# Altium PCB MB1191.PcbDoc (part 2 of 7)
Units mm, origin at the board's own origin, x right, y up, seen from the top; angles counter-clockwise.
Board outline 130 x 80 mm, 8 copper layers (Top, F2, F3, F4, F5, F6, F7, Bottom), stack 1.115 mm thick; 358 components, 347 nets, 1452 pads, 1074 vias.
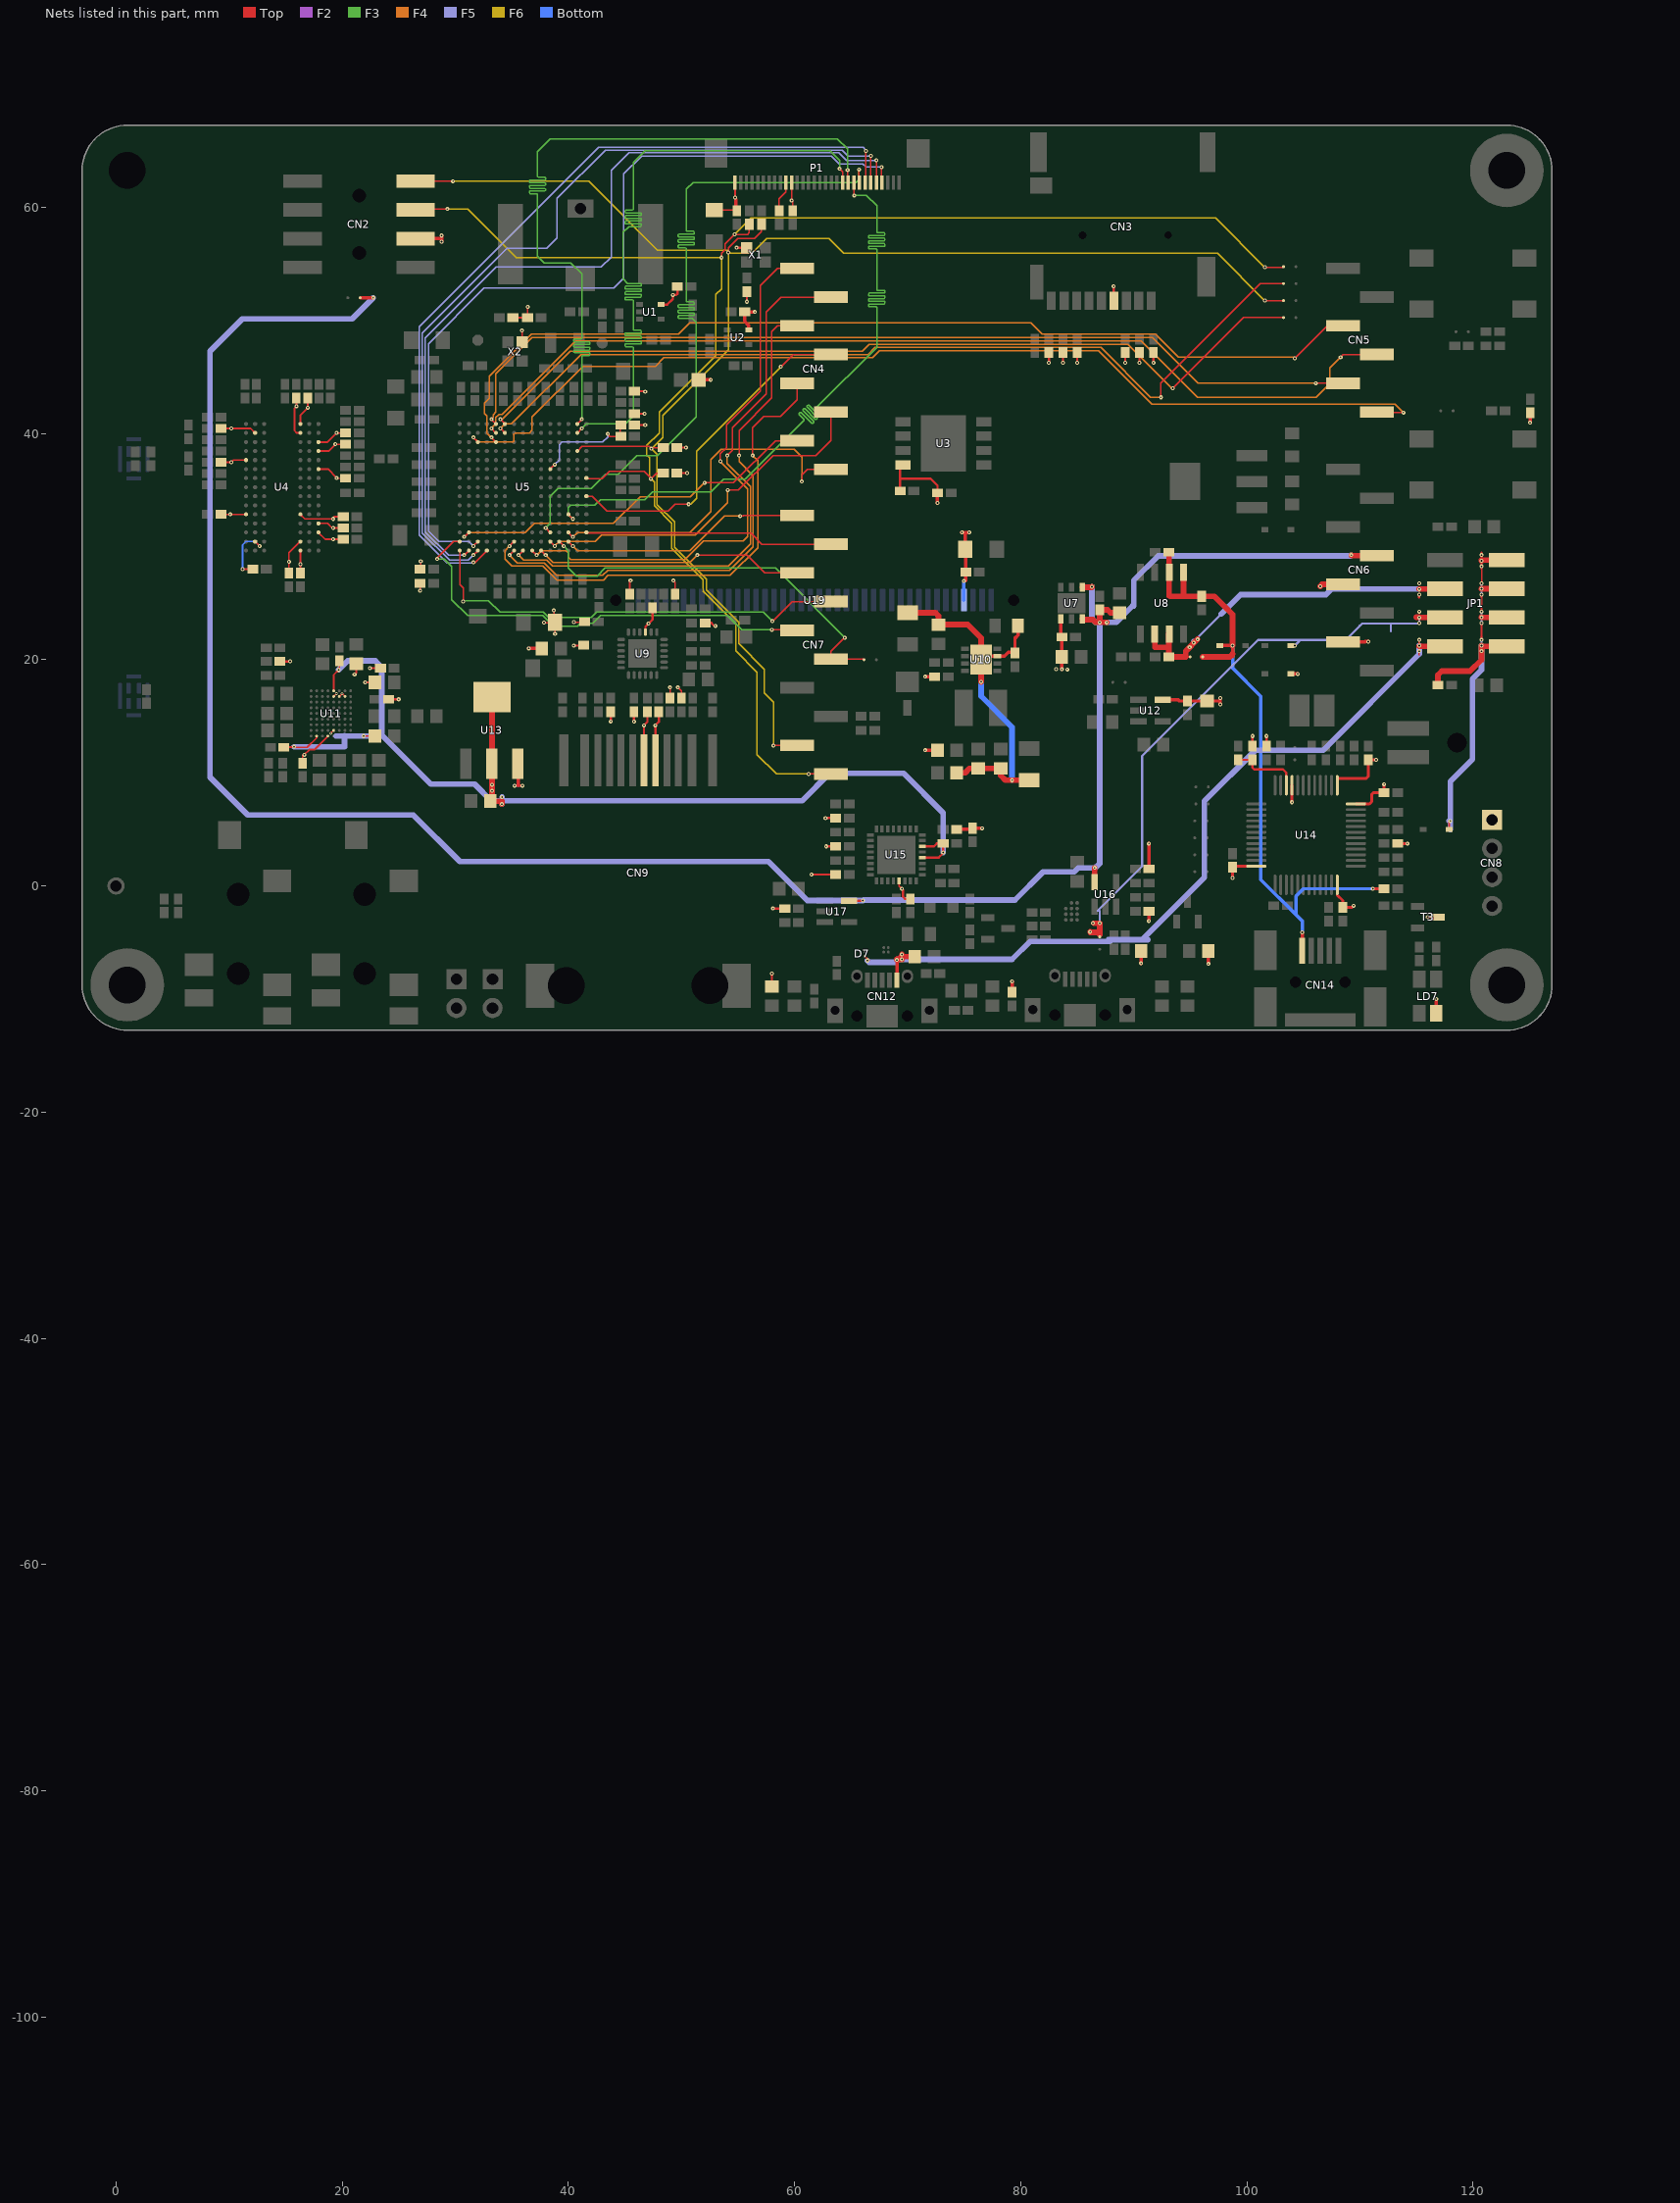
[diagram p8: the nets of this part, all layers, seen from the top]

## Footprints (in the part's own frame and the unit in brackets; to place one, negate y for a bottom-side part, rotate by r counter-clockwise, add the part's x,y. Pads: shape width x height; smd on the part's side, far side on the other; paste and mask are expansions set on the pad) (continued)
QFN24_0R5_4X4 [mm]
  oval 0.69x0.28 smd: 1(-1.9,1.25) 2(-1.9,0.75) 3(-1.9,0.25) 4(-1.9,-0.25) 5(-1.9,-0.75) 6(-1.9,-1.25) 13(1.9,-1.25) 14(1.9,-0.75) 15(1.9,-0.25) 16(1.9,0.25) 17(1.9,0.75) 18(1.9,1.25)
  oval 0.28x0.69 smd: 7(-1.25,-1.9) 8(-0.75,-1.9) 9(-0.25,-1.9) 10(0.25,-1.9) 11(0.75,-1.9) 12(1.25,-1.9) 19(1.25,1.9) 20(0.75,1.9) 21(0.25,1.9) 22(-0.25,1.9) 23(-0.75,1.9) 24(-1.25,1.9)
  rect 2.5x2.5 smd: 25(0,0)
  silkscreen extent -2.82,-2.5 2.5,2.5
QFN32_0R5_5X5 [mm]
  rect 0.6x0.3 smd: 1(-2.3,1.75) 2(-2.3,1.25) 3(-2.3,0.75) 4(-2.3,0.25) 5(-2.3,-0.25) 6(-2.3,-0.75) 7(-2.3,-1.25) 8(-2.3,-1.75) 17(2.3,-1.75) 18(2.3,-1.25) 19(2.3,-0.75) 20(2.3,-0.25) 21(2.3,0.25) 22(2.3,0.75) 23(2.3,1.25) 24(2.3,1.75)
  rect 0.3x0.6 smd: 9(-1.75,-2.3) 10(-1.25,-2.3) 11(-0.75,-2.3) 12(-0.25,-2.3) 13(0.25,-2.3) 14(0.75,-2.3) 15(1.25,-2.3) 16(1.75,-2.3) 25(1.75,2.3) 26(1.25,2.3) 27(0.75,2.3) 28(0.25,2.3) 29(-0.25,2.3) 30(-0.75,2.3) 31(-1.25,2.3) 32(-1.75,2.3)
  rect 3.4x3.4 smd: 33(0,0)
  silkscreen extent -3.05,-3.05 3.05,3.05
"QFP48 7X7" [mm]
  oval 1.803x0.257 smd: 1(-4.4,2.75) 12(-4.4,-2.75) 25(4.4,-2.75) 36(4.4,2.75)
  oval 1.803x0.254 smd: 2(-4.4,2.25) 3(-4.4,1.75) 4(-4.4,1.25) 5(-4.4,0.75) 6(-4.4,0.25) 7(-4.4,-0.25) 8(-4.4,-0.75) 9(-4.4,-1.25) 10(-4.4,-1.75) 11(-4.4,-2.25) 26(4.4,-2.25) 27(4.4,-1.75) 28(4.4,-1.25) 29(4.4,-0.75) 30(4.4,-0.25) 31(4.4,0.25) 32(4.4,0.75) 33(4.4,1.25) 34(4.4,1.75) 35(4.4,2.25)
  oval 0.257x1.803 smd: 13(-2.75,-4.4) 24(2.75,-4.4) 37(2.75,4.4) 48(-2.75,4.4)
  oval 0.254x1.803 smd: 14(-2.25,-4.4) 15(-1.75,-4.4) 16(-1.25,-4.4) 17(-0.75,-4.4) 18(-0.25,-4.4) 19(0.25,-4.4) 20(0.75,-4.4) 21(1.25,-4.4) 22(1.75,-4.4) 23(2.25,-4.4) 38(2.25,4.4) 39(1.75,4.4) 40(1.25,4.4) 41(0.75,4.4) 42(0.25,4.4) 43(-0.25,4.4) 44(-0.75,4.4) 45(-1.25,4.4) 46(-1.75,4.4) 47(-2.25,4.4)
  silkscreen extent -3.96,-2.98 2.97,3.96
RCA_SMD [mm]
  rect 1.6x2.3 hole 1 square mask+0.05: 1(0,0)
  rect 7.1x2.2 smd mask+0.05: 1(3.15,6.2) 1(3.15,-6.2)
  rect 2.2x2.6 smd mask+0.05: 2(6.2,0)
  silkscreen extent -8.5,-5 4.98,5, body extent -8.52,-7 6.5,7, height 12.1
RJ45_HR961160C [mm]
  rect 0.8x4.6 smd: 1(6.579,19.914) 2(4.75,19.914) 11(-4.75,19.914) 12(-6.579,19.914)
  rect 0.6x4.6 smd: 3(3.556,19.914) 4(2.54,19.914) 5(1.524,19.914) 6(0.508,19.914) 7(-0.508,19.914) 8(-1.524,19.914) 9(-2.54,19.914) 10(-3.556,19.914)
  rect 2.5x3.9 smd: 13(8.687,0) 14(-8.687,0)
  round 2.5 hole 3.25 unplated: 15(-6.35,0) 16(6.35,0)
  silkscreen extent -10.67,-5.28 10.67,20.12
SIP1/2.54 [mil]
  round 60 hole 39.37: 1(0,0)
  silkscreen extent -45,-45 45,45
SIP2/2.54 [mil]
  rect 70x70 hole 39.37: 1(0,0)
  round 70 hole 39.37: 2(100,0)
  silkscreen extent -50,-50 150,50
SMDTEST-1MM [mil]
  round 39 smd: 1(0,0)
SO-8 [mil]
  rect 24x60 smd: 1(-75,-107.5) 2(-25,-107.5) 3(25,-107.5) 4(75,-107.5) 5(75,107.5) 6(25,107.5) 7(-25,107.5) 8(-75,107.5)
  silkscreen extent -118,-102 100,68
SOD323/A [mm]
  rect 0.6x0.45 smd: 1(1.143,0) 2(-1.143,0)
  silkscreen extent -0.46,-0.57 0.56,0.57
SOT23 [mm]
  rect 1.2x0.6 smd: 1(-0.9,0.95) 2(-0.9,-0.95) 3(0.9,0)
  silkscreen extent 0.1,-1.5 0.7,1.5
SOT23-5L [mm]
  rect 0.55x1.45 smd: 1(-0.95,-1.075) 2(0,-1.075) 3(0.95,-1.075) 4(0.95,1.075) 5(-0.95,1.075)
  silkscreen extent -1.5,-2.1 1.5,2
SOT353 [mm]
  rect 0.42x0.6 smd: 1(-0.65,-0.95) 2(0,-0.95) 3(0.65,-0.95) 4(0.65,0.95) 5(-0.65,0.95)
  silkscreen extent -1.4,-1.8 1.5,1.8
SOT-223 [mm]
  rect 2.7x1 smd: 1(-2.95,2.3) 2(-2.95,0) 3(-2.95,-2.3)
  rect 2.7x3.3 smd: 4(2.95,0)
  silkscreen extent -3.08,-3.35 1.3,3.47
SSM-104-L-DH [mm]
  rect 1.2x3.4 smd: 1(3.81,-5) 2(3.81,5) 3(1.27,-5) 4(1.27,5) 5(-1.27,-5) 6(-1.27,5) 7(-3.81,-5) 8(-3.81,5)
  round 0.8 hole 1.2 unplated: 9(2.54,0) 10(-2.54,0)
  silkscreen extent -5.08,-3.18 5.08,3.18
TAN-A [mil]
  rect 50x60 smd: 1(55,0) 2(-55,0)
  silkscreen extent -94,-43 102,43
TSM-102-01-F-SH-A [mm]
  round 0 hole 1.73 unplated mask+0.05: 0(0,0)
  rect 3.68x1.27 smd paste+0 mask+0.05: 1(-4.3,1.27) 2(-4.3,-1.27)
  silkscreen extent -2.3,-2.54 7.11,2.54, body extent -5.84,-2.54 7.11,2.54, height 3.05
TSM-104-01-X-DV [mil]
  rect 50x124 smd: 1(-150,-107.5) 2(-150,107.5) 3(-50,-107.5) 4(-50,107.5) 5(50,-107.5) 6(50,107.5) 7(150,-107.52) 8(150,107.52)
  silkscreen extent -200,-100 200,100
USB-MICRO-AB [mm]
  rect 1.35x0.4 smd: 1(0,-1.3) 2(0,-0.65) 3(0,0) 4(0,0.65) 5(0,1.3)
  rect 2x2.8 smd: 6(-3.2,0)
  rect 2.15x1.4 hole 0.8 slot 1.4 at 0 deg copper offset -0.05,0: 6(-2.675,4.175) 6(-2.675,-4.175)
  oval 1.2x1 hole 0.65 slot 0.85 at 0 deg: 6(0.325,2.225) 6(0.325,-2.225)
  round 0.8 hole 1 unplated: 11(-3.175,2.225) 12(-3.175,-2.225)
  silkscreen extent -4.9,-4 -0.3,4
USB-MINI-B-SMD [mm]
  rect 0.5x2.3 smd: 1(1.597,-2.75) 2(0.797,-2.75) 3(-0.003,-2.75) 4(-0.803,-2.75) 5(-1.603,-2.75)
  rect 2x3.5 smd: 6(-4.853,-2.8) 6(-4.853,2.2) 6(4.847,-2.8) 6(4.847,2.2)
  rect 6.2x1.2 smd: 6(0,3.35)
  round 0.5 hole 1 unplated: 11(2.194,0) 12(-2.2,0)
  silkscreen extent -3.85,-4.76 3.85,5.9
W-PDFN-8_8X6_P127 [mm]
  rect 1.35x0.8 smd mask+0.05: 1(-3.575,1.905) 2(-3.575,0.635) 3(-3.575,-0.635) 4(-3.575,-1.905) 5(3.575,-1.905) 6(3.575,-0.635) 7(3.575,0.635) 8(3.575,1.905)
  rect 4x5 smd mask+0.05: 9(0,0)
  silkscreen extent -4.47,-3 4,3, body extent -4,-3 4,3, height 0.81
XTAL_2SM_3R2X1R5 [mm]
  rect 1x1.8 smd: 1(-1.25,0) 2(1.25,0)
  silkscreen extent -2.39,-1.37 2.39,1.37
XTAL_2SM_3R2X2R5 [mm]
  rect 1.8x2.8 smd: 1(-1.1,0) 2(1.1,0)
  silkscreen extent -2.5,-1.8 2.5,1.8

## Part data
B1: "Non-Open Push-Button 0.1A 24V", Manuf_1=wealthmetal, Manuf_2=FARNELL, Manuf_Part_1=TD0341X-G01-BLU, Manuf_Part_2=535-930
B2: "Non-Open Push-Button 0.1A 24V", Manuf_1=wealthmetal, Manuf_2=FARNELL, Manuf_Part_1=TD0341X-G01-BLA, Manuf_Part_2=535-930
C1 C63 C73: library part Cap_10uF_POL_10%_TANA, "Polarized Capacitor,10uF,10V,10%,typeA,VISHAY", Manuf_1=VISHAY, Manuf_Part_1=293D106X9010A2TE3
C2 C3 C4 C5 C7 C10 C11 C15 C16 C18 C19 C20 C21 C22 C23 C24 C25 C26 C27 C28 C30 C31 C32 C33 C34 C35 C36 C37 C38 C39 C40 C42 C43 C44 C45 C46 C50 C51 C52 C53 C55 C56 C57 C58 C59 C60 C61 C68 C70 C72 C74 C76 C77 C81 C82 C83 C84 C85 C92 C98 C101 C102 C103 C109 C110 C111 C113 C115 C116 C117 C118 C120 C121 C122 C123: library part Cap_100nF_X7R_10%_0402, "Capacitor,100nF,16V,X7R,10%,0402,YAGEO", Manuf_1=YAGEO, Manuf_Part_1=CC0402KRX7R7BB104
C6 C9: library part Cap_22nF_X7R_10%_0402, "Capacitor,22nF,16V,X7R,10%,0402,YAGEO", Manuf_1=YAGEO, Manuf_Part_1=CC0402KRX7R7BB223
C8 C17: library part Cap_1uF_POL_10%_TANA, "Polarized Capacitor,1uF,16V,10%,typeA,AVX", Manuf_1=AVX, Manuf_Part_1=TAJA105K016R
C12 C13: library part Cap_4.7pF_NPO_-+0.25pF_0402, "Capacitor, 4.7pF, 50V, NPO, -+0.25pF, 0402, YAGEO", Manuf_1=YAGEO, Manuf_Part_1=CC0402CRNPO9BN4R7
C14 C49 C54: library part Cap_4.7uF_POL_10%_TANA, "Polarized Capacitor,4.7uF,16V,10%,typeA,AVX", Manuf_1=AVX, Manuf_Part_1=TAJA475K016R
C29 C41: library part Cap_10uF_X5R_10%_0805, "Capacitor,10uF,25V,X5R,10%,0805,YAGEO", Manuf_1=YAGEO, Manuf_Part_1=CC0805KRX5R8BB106
C47 C48: library part Cap_2.2uF_X7R_10%_1206, "Capacitor,2.2uF,16V, X7R,10%,1206,YAGEO", Manuf_1=YAGEO, Manuf_2=KEMET, Manuf_Part_1=CC1206KKX7R7BB225, Manuf_Part_2=C1206C225K4RAC
C62 C67 C69 C71 C75 C86 C89 C91 C106 C107: library part Cap_1uF_X5R_10%_0603, "Capacitor,1uF,16V,X5R,10%,0603,YAGEO", Manuf_1=YAGEO, Manuf_Part_1=CC0603KRX5R7BB105
C64: library part Cap_4.7uF_X7R_10%_1206, "Capacitor,4.7uF,50V, X7R,10%,1206,AVX", Manuf_1=AVX, Manuf_Part_1=12065C475KAT2A
C65 C94 C96: library part Cap_10nF_X7R_10%_0603, "Capacitor,10nF,50V,X7R,10%,0603,YAGEO", Manuf_1=YAGEO, Manuf_Part_1=CC0603KRX7R9BB103
C66: library part Cap_470pF_X7R_10%_0402, "Capacitor,470pF,16V,X7R,10%,0402,YAGEO", Manuf_1=AVX, Manuf_Part_1=0402YC471KAT4A
C78 C80 C87: library part Cap_2.2uF_X5R_10%_0603, "Capacitor,2.2uF,10V, X5R,10%,0603,YAGEO", Manuf_1=YAGEO, Manuf_2=KEMET, Manuf_Part_1=CC0603KRX5R6BB225, Manuf_Part_2=C0603C225K8PACTU
C79 C88 C93 C104 C105 C112 C114: library part Cap_4.7uF_X5R_10%_0603, "Capacitor,4.7uF,16V, X5R,10%,0603,YAGEO", Manuf_1=YAGEO, Manuf_Part_1=CC0603KRX5R7BB475
C90: library part Cap_NA_0402, "Capacitor,NA,0402"
C95: library part Cap_100nF_X7R_10%_0603, "Capacitor,100nF,16V,X7R,10%,0603,YAGEO", Manuf_1=YAGEO, Manuf_Part_1=CC0603KRX7R9BB104
C97: library part Cap_4.7uF_X5R_10%_1206, "Capacitor,4.7uF,16V, X5R,10%,1206,AVX", Manuf_1=AVX, Manuf_Part_1=1206YD475KAT2A
C99 C100: library part Cap_10pF_NPO_5%_0402, "Capacitor,10pF,50V,NPO,5%,0402,YAGEO", Manuf_1=YAGEO, Manuf_Part_1=CC0402JRNPO9BN100
C108: library part Cap_10uF_X5R_10%_0603, "Capacitor,10uF,6.3V,X5R,10%,0603,YAGEO", Manuf_1=YAGEO, Manuf_Part_1=CC0603KRX5R5BB106
C119: library part Cap_2.2uF_X7R_10%_0805, "Capacitor,2.2uF,16V, X7R,10%,0805,YAGEO", Manuf_1=YAGEO, Manuf_Part_1=CC0805KKX7R7BB225
CN1: "RCA Phono Jack, Right Angle, SMD, Yellow", Manuf_1=Jiubaba, Manuf_Part_1=JBB0819100002
CN2: "Header, 5-Pins, Horizontal Dual row, female SMD", Manuf_1=TOWNES, Manuf_2=SAMTEC, Manuf_Part_2=SSM-104-L-DH
CN3: library part microSD-PJS008-2003, "Memory Card Connectors MicroSD Card Conn Revrs Mnt Push-Push", Manuf_1=YAMAICHI
CN4 CN6: library part F201-1*08MGF-W1-BA, "Header, 8-Pins, Single row, female SMD", Manuf_1=TOWNES, Manuf_2=SAMTEC, Manuf_Part_2=SSW-108-22-L-S-VS
CN5: library part F201-1*06MGF-W1-BA, "Header, 6-Pins, Single row, female SMD", Manuf_1=TOWNES, Manuf_2=SAMTEC, Manuf_Part_2=SSW-106-22-L-S-VS
CN7: library part F201-1*10MGF-W1-BA, "Header, 10-Pins, Single row, female SMD", Manuf_1=TOWNES, Manuf_2=SAMTEC, Manuf_Part_2=SSW-110-22-L-S-VS
CN8: "Header, 4-Pin"
CN9: "100 Base-TX (Fast Ethernet) SMD RJ45 single port (1x1) with LEDS Integrated Magnetics Connector", Manuf_1=HanRun, Manuf_2="Pulse Electronics Corporation", Manuf_3="K.O.D International Holding", Manuf_Part_2=J3011G21DNLT, Manuf_Part_3=RMT-119A-12F6-GY-04
CN10: "Connector Jack Stereo 3.5mm, female SMT, Green (Line output)", Manuf_1=qiaod, Manuf_Part_2=PJ30280-3_GR
CN11: "Connector Jack Stereo 3.5mm, female SMT, Blue (Line input)", Manuf_1=qiaod, Manuf_Part_2=PJ30280-3_BE
CN12 CN13: "USB-MICRO-AB, 47590-0001, SMT, MOLEX", Manuf_1=MOLEX, Manuf_Part_1=47590-0001
CN14: library part "USB-MINI-typeB connector", "USB-MINI-typeB connector", Manuf_2=lyconn, Manuf_3=TOWNES, Manuf_Part_1=5075BMR-05-SM, Manuf_Part_2=218205M1110T, Manuf_Part_3=MUSB5QS-BM1H6-NLB-E
D1 D2 D3 D4 D6: Manuf_1=STM
D5: "Low Drop power Schottky rectifier(1A, 40V, 0.4V)", Manuf_1=STM
D7: "Quad bidirectional Transil array for ESD protection", Manuf_1=STM
JP1: library part Header_4X2_SMD, "Header, 4-Pins, Double row Vertical, SMD, 2.54", Manuf_1=SAMTEC
JP2: library part JP2_CMS, "Header, 2-Pins, Single row Horizontal SMD, 2.54", Manuf_1=SAMTEC
JP3 JP4: library part Jumper2
L1 L4 L5: library part BEAD_600R_350MA_0603, "Bead,600R,350mA,0603,FCM1608KF-601T03,Tai-tech", Manuf_1=Tai-tech, Manuf_2=TDK, Manuf_3=MURATA, Manuf_Part_2=MPZ1608S300A, Manuf_Part_3=BLM18PG121SN1D
L2 L6 L7: library part BEAD_120R_2A_0603, "Bead,120R,2A,0603,BLM18PG121SN1D,MURATA", Manuf_1=MURATA, Manuf_2=TDK, Manuf_3=Tai-tech, Manuf_Part_2=MPZ1608S300A, Manuf_Part_3=FCM1608KF-601T03
L3: library part Ind_4.7uH_1A_30%, "FIXED IND 4.7UH 1A 180 MOHM 30% SMD", Manuf_1=MURATA, Manuf_Part_1=LQH32PN4R7NN0L
LD1 LD4 LD5: library part LED_green, "LED, green, 0603", Manuf_1=everlight, Manuf_Part_1=19-213SYGC/S530-E2/TR8
LD2 LD3 LD6: library part LED_red, "LED, red, 0603", Manuf_1=everlight, Manuf_Part_1=19-217/R6C-AL1M2VY/3T
LD7: "Bicolor Led", Manuf_1="Avago Technologies", Manuf_2=everluck, Manuf_Part_1=HSMF-A201-A00J1, Manuf_Part_2=LE-RGW35280
P1: "TOWNES -  Connector FFC/FPC ZIF 0.5mm 30 pins, Lower Contacts", Manuf_1=TOWNES, Manuf_Part_2=TFP-A330ZH-BT1-ECX
R1 R2 R3 R7 R10 R29 R30 R33 R58 R78 R114 R118 R127: library part Res_100_1%_0402, "Resistor,100,0402,1%,YAGEO", Manuf_1=YAGEO, Manuf_Part_1=RC0402FR-07100RL
R4 R5 R18 R19 R20 R23 R24 R25 R26 R27 R34 R36 R37 R38 R39 R40 R41 R43 R45 R47 R48 R49 R50 R51 R52 R53 R55 R56 R57 R60 R87 R88 R95 R101 R116 R120: library part Res_10K_1%_0402, "Resistor,10K,0402,1%,YAGEO", Manuf_1=YAGEO, Manuf_Part_1=RC0402FR-0710KL
R6: library part Res_75_1%_0402, "Resistor,75,0402,1%,YAGEO", Manuf_1=YAGEO, Manuf_Part_1=RC0402FR-0775RL
R8 R12 R35 R42 R63 R80 R100 R103 R106 R111: library part Res_NA_0402, "Resistor,[NA],0402"
R9 R22: library part Res_1M_1%_0402, "Resistor,1M,0402,1%,YAGEO", Manuf_1=YAGEO, Manuf_Part_1=RC0402FR-071ML
R11 R31 R32 R44 R64 R76 R81 R83 R96 R104 R107 R109 R110 R113 R117 R119 R125 R130 R132 R133: library part Res_0_5%_0402, "Resistor,0,0402,5%,YAGEO", Manuf_1=YAGEO, Manuf_Part_1=RC0402JR-070RL
R13 R14 R15 R16 R17 R124 R126 R134: library part Res_47K_1%_0402, "Resistor,47K,0402,1%,YAGEO", Manuf_1=YAGEO, Manuf_Part_1=RC0402FR-0747KL
R21 R28: library part Res_0_5%_0603, "Resistor,0,0603,5%,YAGEO", Manuf_1=YAGEO, Manuf_Part_1=RC0603JR-070RL
R46 R54 R61 R62 R79 R108: library part Res_2K7_1%_0402, "Resistor,2K7,0402,1%,YAGEO", Manuf_1=YAGEO, Manuf_Part_1=RC0402FR-072K7L
R59: library part Res_510_1%_0402, "Resistor,510,0402,1%,YAGEO", Manuf_1=YAGEO, Manuf_Part_1=RC0402FR-07510L
R65 R128: library part Res_1K5_1%_0402, "Resistor,1K5,0402,1%,YAGEO", Manuf_1=YAGEO, Manuf_Part_1=RC0402FR-071K5L
R66 R69 R71: library part Res_33_1%_0402, "Resistor,33,0402,1%,YAGEO", Manuf_1=YAGEO, Manuf_Part_1=RC0402FR-0733RL
R67 R68 R70 R73 R74 R77 R85 R97 R98 R112: library part Res_4K7_1%_0402, "Resistor,4K7,0402,1%,YAGEO", Manuf_1=YAGEO, Manuf_Part_1=RT0402FRE074K7L
R72 R82 R99 R105 R131 R135: library part Res_100K_1%_0402, "Resistor,100K,0402,1%,YAGEO", Manuf_1=YAGEO, Manuf_Part_1=RT0402FRE07100KL
R75: library part Res_10_1%_0805, "Resistor,10,0805,1%,Stackpole,1/4W", Manuf_1="Stackpole Electronics Inc", Manuf_Part_1=RNCP0805FTD10R0
R84: library part Res_12K1_1%_0603, "Resistor,12K1,0603,1%,VISHAY", Manuf_1=VISHAY, Manuf_Part_1="MCT 0603-50 1% P5 12K1"
R86: library part Res_1K_1%_0402, "Resistor,1K,0402,1%,YAGEO", Manuf_1=YAGEO, Manuf_Part_1=RC0402FR-071KL
R89 R94 R138 R139 R141: library part Res_330_1%_0402, "Resistor,330,0402,1%,YAGEO", Manuf_1=YAGEO, Manuf_Part_1=RC0402FR-07330RL
R90 R91 R92 R93: library part Res_50_1%_0402, "Resistor,50,0402,1%,YAGEO", Manuf_1=YAGEO, Manuf_Part_1=RC0402FR-0749R9L
R102 R121: library part Res_20_1%_0402, "Resistor,20,0402,1%,YAGEO", Manuf_1=YAGEO, Manuf_Part_1=RC0402FR-0720RL
R115: library part Res_8K06_1%_0402, "Resistor,8K06,0402,1%,YAGEO", Manuf_1=YAGEO, Manuf_Part_1=RC0402FR-078K06L
R122: library part Res_3K3_1%_0402, "Resistor,3K3,0402,1%,YAGEO", Manuf_1=YAGEO, Manuf_Part_1=RC0402FR-073K3L
R123: library part Res_820_1%_0805, "Resistor,820,0805,1%,YAGEO", Manuf_1=YAGEO, Manuf_Part_1=RC0805FR-07820RL
R129: library part Res_36K_1%_0402, "Resistor,36K,0402,1%,YAGEO", Manuf_1=YAGEO, Manuf_Part_1=RC0402FR-0736KL
R136: library part Res_330_1%_0603, "Resistor,330,0603,1%,YAGEO", Manuf_1=YAGEO, Manuf_Part_1=RT0603FRE07330RL
R137 R140: library part Res_620_1%_0603, "Resistor,620,0603,1%,VISHAY", Manuf_1="VISHAY DRALORIC", Manuf_Part_1=CRCW0603620RFKEA
SB1 SB2 SB4 SB9 SB11: library part SB_OFF
SB3 SB5 SB6 SB7 SB8 SB10 SB12 SB13 SB14 SB15 SB16 SB17 SB18: library part SB_ON
T1 T2 T3: "NPN Bipolar Transistor", Manuf_1=NXP, Manuf_Part_1=BSR14
TP1 TP2: "Test Point"
TP3: library part TP1, "Test Point"
U1 U2: "Single inverter gate with a standard push-pull output. (1.65V to 5.5V)", Manuf_1=DIODES, Manuf_Part_1=74LVC1G04SE-7
U3: library part MT25QL128ABA1EW9-0SIT, "128Mb, 3V, Multiple I/O Serial Flash Memory, Quad/Dual", Manuf_1=Winbond
U4: library part MT48LC4M32B2B5-6A, "SDRAM 128MBIT (4M x 32) 166MHZ 90-VFBGA (8x13)", Manuf_1=ISSI, Manuf_Part_1=IS42S32400F-6BL
U5: library part STM32F746NGH6U, "STM32F746NGH6 (STM32F7 Birdie) TBGA216", Manuf_1=STM
U6: "IC REG LDO 5V 0.8A SOT223", Manuf_1=STM
U7: library part LD39050P, "Ultra low drop-low , 500 mA low quiescent current", Manuf_1=STM
U8: "1.2 A current limited high-side power switch with thermal shutdown", Manuf_1=STM
U9: "LAN8742A-CZ-TR - Small Footprint RMII 10/100 Ethernet, Transceiver with HP Auto-MDIX and flexPWR Technology SQFN-24", Manuf_1=MICROCHIP
U10: "White LED power supply for large display backlight, QFN8", Manuf_1=STM
U11: "Multi-Channel Audio Hub CODEC for Smartphones", Manuf_1="Cirrus Logic"
U12: "Ultra low drop-low noise BiCMOS voltage, regulators low ESR capacitors compatible", Manuf_1=STM
U13: "LOW DROP FIXED AND ADJUSTABLE POSITIVE VOLTAGE REGULATORS (1.8 Volts)", Manuf_1=STM
U14: "Medium-density performance line ARM-based 32-bit MCU with 128KB Flash", Manuf_1=STM
U15: "USB3320C,  Hi-Speed USB Host, Device or OTG PHY with ULPI Low Pin Interface", Manuf_1=MICROCHIP, Manuf_Part_1=USB3320C-EZK-TR
U16 U17: "Enhanced single channel power switches", Manuf_1=STM
U18: "2-line IPAD, EMI filter including ESD protection", Manuf_1=STM
U19: library part HT043C, "4.3 inch TFT 480*272 pixels with LED Backlight and Capacitive touch panel, high luminance", Manuf_1="Shenzhen GJX Electronics Technology Co.,Ltd"
U20 U21: "MEMS audio sensor omnidirectional digital microphone for industrial applications", Manuf_1=STMICROELECTRONICS
U22: "3-line low capacitance protection for high speed USB", Manuf_1="ON SEMICONDUCTOR"
X1: library part OSC_24M_NZ2520SB, "Oscillator 24.00Mhz, -+50PPM, 3.3V, Temp -55 to +125°C", Manuf_1=NDK, Manuf_Part_1="NZ2520SH 24MHz END4869D"
X2: library part OSC_25M_NZ2520SB, "Oscillator 25.00Mhz, -+50PPM, 3.3V, Temp -55 to +125°C", Manuf_1=NDK, Manuf_Part_1="NZ2520SH 25MHz END4869C"
X3: library part XTAL_32K_NX3215SA, "Crystal 32.768kHz, 6pF, -+20PPM, R=50K, SMD", Manuf_1=NDK, Manuf_Part_1="NX3215SA 32.768KHz EXS00A-MU00525"
X4: library part XTAL_8M_NX3225GD, "Crystal 8Mhz, 8pF, -+50PPM, SMD", Manuf_1=NDK, Manuf_Part_1="NX3225GD 8MHz EXS00A-CG04874", Manuf_Part_2=NX3225GD-8.000M-STD-CRA-3

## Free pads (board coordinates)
  round 6.5 hole 3.25: 1(1,-8.75) 1(123,-8.75) 1(123,63.25)
  round 0.508 on Mech6: 1(17.42,-110.927)
  round 0.508 on Mech16: 1(134.189,-110.927)

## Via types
v1: diameter 0.35, hole 0.15, Top to Bottom, tented both sides, 1046 vias
v2: diameter 0.25, hole 0.1, Top to Bottom, tented both sides, 26 vias
v3: diameter 0.3, hole 0.1, Top to Bottom, tented both sides, 2 vias

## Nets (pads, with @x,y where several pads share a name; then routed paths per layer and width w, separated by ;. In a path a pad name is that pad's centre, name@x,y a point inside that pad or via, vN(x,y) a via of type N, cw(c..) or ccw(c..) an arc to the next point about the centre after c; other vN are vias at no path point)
1V8: C70.1 C92.1 C93.1 C108.2 C110.2 U11.D1 U11.D8 U11.G9 U13.2 U13.4 U15.28 U15.30 | length 102.9
  Top w0.15: v1(15.75,12.3) 14.85,12.3 C92.1@14.85,12.25 16.9,12.25 17.75,13.1 U11.G9@17.75,13.25 ; v2(19,13.5) U11.D8@19.25,13.75 ; U11.D1@19.25,17.25 19.25,18.65 v1(19.7,19.1) 19.75,19.15 C70.1@19.75,19.9 ; v1(21.9,13.25) C93.1@22.9,13.25
  Top w0.2: U15.28@71.3,2.5 72.75,2.5 73.15,2.9 v1(73.15,2.95) C110.2@73.15,3.75 72.6,3.75 72.35,3.5 U15.30@71.3,3.5
  Top w0.5: U13.4@33.25,16.7 U13.2@33.25,10.8 v1@33.25,8.94 ; v1(33.26,8.95) v1@33.25,8.94 ; v1(34.13,7.23) 34.13,7.48 ; 34.14,7.48 34.13,7.48 ; v1@33.25,8.94 v1(33.25,8.4) 33.25,7.65 C108.2@33.1,7.5 33.1,7.48 34.13,7.48
  F5 w0.5: v1(15.75,12.3) 20.2,12.3 20.2,13.25 ; 19.45,13.25 20.2,13.25 ; v1(19.7,19.1) 20.5,19.9 22.95,19.9 23.5,19.35 23.5,13.35 23.6,13.25 ; v1(34.13,7.23) v1@34.14,7.23 ; v1(34.14,7.85) 34.14,7.51 ; v1(73.15,2.95) 73.15,6.45 69.65,9.95 63.1,9.95 60.68,7.53 34.15,7.53 34.15,7.23 v1@34.14,7.23 ; 20.2,13.25 20.25,13.25 ; 20.2,13.25 20.2,13.3 20.25,13.25 ; 20.25,13.25 v1(21.9,13.25) 23.6,13.25 ; 23.6,13.25 27.85,9 31.71,9 33.2,7.51 34.14,7.51 ; v1@34.14,7.23 34.14,7.51
3V3: C1.1 C2.2 C3.2 C4.2 C5.2 C7.2 C15.2 C16.2 C26.2 C27.2 C28.2 C31.2 C34.2 C38.2 C42.2 C43.2 C45.2 C46.2 C49.1 C50.2 C51.2 C52.2 C53.2 C60.2 C63.1 C68.2 C71.2 C72.1 C75.2 C79.1 C82.2 C83.2 C103.1 C111.1 CN2.5 CN3.4 CN6.2 CN6.4 CN9.5 CN9.6 L2.2 L4.1 P1.20 P1.30 R4.1 R5.1 R12.2 R13.2 R14.2 R15.2 R16.2 R17.2 R21.2 R34.2 R38.1 R39.2 R42.1 R46.2 R54.2 R57.2 R61.2 R62.2 R65.2 R67.2 R70.2 R73.2 R77.2 R80.2 R85.2 R87.2 R90.1 R91.1 R92.1 R93.1 R104.2 R107.2 R110.2 R113.2 R116.2 R122.1 R126.2 R136.2 R137.2 R140.2 R141.2 U1.5 U2.5 U3.8 U4.A7 U4.B2 U4.B7 U4.C9 U4.D9 U4.E1 U4.F9 U4.L1 U4.L7 U4.M9 U4.N9 U4.P2 U4.P7 U4.R7 U7.4 U9.9 U11.B2 U11.C2 U11.D2 U11.E9 U13.3 U19.4 X1.4 X2.4 | length 155.6
  Top w0.12: U4.P2@12.3,30.45 v1(12.7,30.05) ; v1(37.85,23.275) 38.809,23.275 C63.1@38.824,23.29 ; v1(38.725,24.35) 38.725,23.389 C63.1@38.824,23.29 ; v1(38.824,22.269) C63.1@38.824,23.29 ; v1(40.5,23.32) 41.41,23.32 R65.2@41.44,23.35 ; R65.2@41.25,23.5 R65.2@41.3,23.55 ; R65.2@41.42,23.25 R65.2@41.44,23.23
  Top w0.15: C42.2@9.3,32.85 v1(10.1,32.85) U4.L1@11.5,32.85 ; C31.2@9.3,37.45 v1(10.2,37.45) 10.4,37.65 U4.E1@11.5,37.65 ; C26.2@9.3,40.45 v1(10.2,40.45) 11.9,40.45 U4.B2@12.3,40.05 ; C51.2@15.3,27.65 v1(15.3,28.65) 15.3,29.45 U4.P7@16.3,30.45 ; C52.2@16.3,27.65 v1(16.3,28.45) U4.R7@16.3,29.65 ; U4.L7@16.3,32.85 16.7,32.45 v1@19.1,32.45 ; C103.1@16.5,10.85 16.5,11.551 16.65,11.551 v1(16.65,11.6) 17.1,12.05 17.55,12.05 U11.E9@18.75,13.25 ; U4.N9@17.9,31.25 18.5,30.65 v1(19.2,30.65) C46.2@20.1,30.65 ; U4.M9@17.9,32.05 18.7,32.05 19.1,31.65 v1(19.2,31.65) C45.2@20.1,31.65 ; v1(19.2,32.45) v1@19.1,32.45 ; U11.D2@19.25,16.75 v2(19.5,17) ; v1(19.5,36.05) 19.399,36.05 19.449,36 19.503,36.003 C34.2@20.3,36.05 ; U11.C2@19.75,16.75 v2(20,17) U11.B2@20.25,16.75 ; C43.2@20.1,32.65 19.3,32.65 v1@19.1,32.45 ; v1(26.9,26.1) R62.2@26.9,26.75 ; R61.2@26.9,28 26.95,28 v1(26.95,28.7) ; R5.1@35.1,50.25 C5.2@36.4,50.25 v1(36.4,51.2) ; v1(35.9,49.1) 35.925,49.1 X2.4@35.925,48.075 ; R67.2@45.436,25.786 45.436,27 v1(45.5,27) ; R42.1@45.85,40.75 v1(46.8,40.75) ; R38.1@45.85,41.75 v1(46.75,41.75) ; R34.2@45.85,43.75 46.8,43.75 v1(46.8,43.7) ; R92.1@49,16.6 v1(49,17.55) ; v1(49.3,27) 49.3,26.95 49.436,26.814 R70.2@49.436,25.786 ; R46.2@49.6,38.75 v1(50.4,38.75) ; v1(49.7,17.55) 50,17.25 R93.1@50,16.6 ; C1.1@52.9,59.747 54.75,59.747 v1(54.75,60.85) ; P1.30@54.75,62.175 v1(54.75,60.85) ; C2.2@54.9,59.7 54.9,60.7 v1(54.75,60.85) ; R140.2@58,-8.9 v1(58,-7.75) ; P1.20@59.75,62.175 v1(59.75,60.6) 59.85,60.6 C3.2@59.85,59.7
  Top w0.165: C15.2@15.95,43.15 15.95,42.414 v1(15.967,42.414) 15.789,42.236 15.789,40.26 16,40.05 U4.B7@16.3,40.05 ; U4.A7@16.3,40.85 16.3,41.616 v1(16.963,42.279) C16.2@16.95,43.15 ; U4.F9@17.9,36.85 18.75,36.85 19.5,36.1 v1(19.5,36.05) ; U4.D9@17.9,38.45 18.8,38.45 v1(19.4,39.05) 19.413,39.037 C28.2@20.3,39.05 ; U4.C9@17.9,39.25 18.7,39.25 v1(19.5,40.05) 19.513,40.037 C27.2@20.3,40.05
  Top w0.2: v1(11.2,28) C50.2@12.1,28 ; R80.2@14.5,19.85 v1(15.4,19.85) ; v1(21.1,18.7) 21.25,18.85 C71.2@21.25,19.65 ; v1(22.05,18) C79.1@22.9,18 ; v1(22.45,19.25) C72.1@23.4,19.25 ; R87.2@24.1,16.5 v1(25,16.5) ; 35.58,8.87 v1(35.94,8.87) ; v1(40.475,21.25) 41.15,21.25 R77.2@41.4,21.5 ; R90.1@43.75,15.4 43.76,15.4 v1(43.76,14.54) ; R91.1@45.8,15.4 45.81,15.4 v1(45.81,14.53) ; CN9.6@46.694,11.099 46.694,14.194 v1(46.7,14.2) 47,14.5 C82.2@47,15.4 ; U9.9@46.822,22.439 46.822,22.922 v1(47.1,23.2) 47.45,23.55 C60.2@47.45,24.6 ; CN9.5@47.71,11.099 47.71,14.21 v1(47.7,14.2) 48,14.5 C83.2@48,15.4 ; U1.5@48.2,51.4 48.75,51.4 49.25,51.9 v1(49.25,52.25) 49.55,52.25 49.65,52.35 C4.2@49.65,53 ; R54.2@49.6,36.5 v1(50.5,36.5) ; R73.2@52.1,23.25 52.65,23.25 52.9,23 v1(53,23) ; v1(54.875,56.425) X1.4@55.775,56.425 ; v1(55.8,51.65) R4.1@55.8,52.55 ; v1(58.1,-2) R122.1@59.15,-2 ; v1(61.5,1) R113.2@63.65,1 ; v1(62.75,6) R104.2@63.65,6 ; v1(62.8,3.5) R110.2@63.65,3.5 ; U3.8@69.272,37.269 69.347,37.269 69.347,36 ; C38.2@69.347,34.924 69.347,36 ; R57.2@72.65,34.75 72.65,35.4 72.05,36 69.347,36 ; v1(82.5,46.25) R12.2@82.5,47.15 ; v1(83.75,46.25) R13.2@83.75,47.15 ; v1(85,46.25) R14.2@85,47.15 ; v1(88.225,53.025) 88.225,51.4 CN3.4@88.45,51.175 ; v1(89.25,46.25) R15.2@89.25,47.15 ; v1(90.5,46.25) R16.2@90.5,47.15 ; v1(91.75,46.25) R17.2@91.75,47.15
  Top w0.3: CN2.5@26.5,57.23 28.8,57.23 ; v1(28.8,56.95) 28.8,57.23 ; v1(28.8,57.5) 28.8,57.23 ; U13.3@35.55,10.8 35.58,10.8 35.58,8.87 ; v1(36.5,21) L2.2@37.65,21 ; R21.2@51.525,44.75 v1(52.6,44.75) ; U2.5@55.95,49.15 55.95,49.55 55.6,49.9 C7.2@55.6,50.75 v1(56.5,50.75) ; v1(71.55,12) L4.1@72.65,12 ; v1(71.55,18.5) R85.2@72.4,18.5 ; v1(72.65,33.85) R57.2@72.65,34.75 ; R107.2@74.35,5 75.75,5 C111.1@75.75,5.1 v1(76.6,5.1) ; v1(74.8,31.25) 75.103,31.25 ; v1(74.975,26.95) 75.15,27 C53.2@75.15,27.75 75.15,29.75 C49.1@75.103,29.75 75.103,31.25 ; v1(75.45,31.25) 75.103,31.25 ; R141.2@79.25,-9.4 v1(79.25,-8.45) ; U7.4@83.55,23.6 83.55,22 C68.2@83.65,22 C75.2@83.65,20.25 v1(83.65,19.15) ; v1(90.65,-6.85) R136.2@90.65,-5.75 ; v1(91.35,-3.1) R126.2@91.35,-2.25 ; R116.2@91.35,1.5 v1(91.35,3.75) ; v1(96.6,-6.9) R137.2@96.6,-5.75 ; CN6.2@108.5,21.58 110.45,21.58 110.45,21.6 v1(110.75,21.6) ; v1(125.05,40.95) 125.071,40.95 R39.2@125.071,41.821
  Top w0.5: v1(106.5,26.5) 106.66,26.66 CN6.4@108.5,26.66
  F2 w0.2: v1(35.24,8.87) v1(35.94,8.87)
  Bottom w0.15: v1(11.2,28) 11.2,30.15 11.5,30.45 12.3,30.45 v1(12.7,30.05)
  Bottom w0.3: U19.4@74.975,25.25 v1(74.975,26.95)
  other v1: 84.12,19.14 83.14,19.17
3V3_ST_LINK: C85.2 C86.1 C101.2 C109.2 C113.2 C118.1 CN8.1 LD7.4 R98.1 R99.2 R109.2 T3.3 U12.5 U14.1 U14.9 U14.24 U14.36 U14.48 | length 28
  Top w0.25: v1(98.75,0.7) C113.2@98.75,1.65 98.75,1.75 U14.24@100.85,1.75 ; R98.1@100.5,12.35 v1(100.5,13.25) ; R99.2@101.75,12.35 v1(101.75,13.25) ; v1(104,7.4) U14.9@104,8.9 ; U14.36@108,0.1 108,-0.8 108.5,-1.3 C118.1@108.5,-1.9 109.3,-1.9 v1(109.45,-1.75) ; U14.1@108,8.9 108,9.5 110.55,9.5 110.75,9.7 C101.2@110.75,11.15 v1(111.45,11.15) ; U14.48@109.65,7.25 110.85,7.25 111.05,7.45 111.05,8.1 111.2,8.25 C109.2@112.15,8.25 v1(112.15,9) ; R109.2@113.35,3.75 v1(114.2,3.75) ; v1(116,-2.75) T3.3@116.9,-2.75
  Top w0.3: U12.5@92.575,16.45 93.95,16.45 94.05,16.35 C85.2@94.75,16.35 97.65,16.35 ; v1(97.65,16.05) 97.65,16.35 ; v1(97.65,16.6) 97.65,16.35 ; LD7.4@116.75,-11.25 v1(116.75,-10)
5V: C61.2 C62.2 C117.1 CN6.5 D6.1 JP1.2 JP1.4 JP1.6 JP1.8 R86.1 SB2.2 U7.1 U7.6 U15.21 U16.5 U17.5 | length 246.6
  Top w0.15: U15.21@69.25,0.45 69.25,0.001 v1(69.5,-0.25) ; 120.72,28.072 120.75,28.042 ; v1(120.75,21.75) v1(120.75,23.25) ; v1(120.75,24.25) v1(120.75,25.75) ; v1(120.75,26.75) 120.771,26.771 120.771,28.021 120.75,28.042 ; v1(120.75,28.75) v1(120.75,28.25) 120.75,28.042 ; v1@120.75,28.81 v1(120.75,29.25) 120.75,29.489
  Top w0.2: U17.5@64.825,-1.3 v1(66.05,-1.3) ; v1(69.5,-0.25) 69.601,-0.35 69.601,-0.951 69.8,-1.15 C117.1@70.25,-1.15 ; D6.1@117.893,5 117.893,5.75 v1(118,5.75)
  Top w0.3: SB2.2@21.6,52 v1(22.75,52)
  Top w0.5: U7.6@85.45,23.6 85.51,23.54 86.39,23.54 86.63,23.3 v1(87,23.3) ; U7.1@85.45,26.4 86.3,26.4 v1(86.3,26.45) ; U16.5@86.55,0.325 v1(86.55,1.6) ; v1(87.62,23.3) v1(87,23.3) ; C62.2@88.75,24.15 87.95,24.15 87.7,24.4 C61.2@87,24.4 v1(87,23.3) ; v1(109.25,29.25) 109.3,29.2 CN6.5@111.5,29.2 ; R86.1@116.9,17.75 116.9,18.65 117.25,19 119.75,19 120.75,20 v1(120.75,20.75) v1@120.75,21.19 ; v1(120.75,21.25) v1@120.75,21.19 ; v1(120.75,23.75) 120.75,23.73 JP1.6@122.981,23.73 ; v1@120.75,26.25 v1(120.75,26.27) JP1.4@122.981,26.27 ; v1(120.75,28.75) 120.75,28.81 JP1.2@122.981,28.81 ; JP1.8@122.981,21.19 v1@120.75,21.19
  F5 w0.15: v1(120.75,21.25) v1(120.75,21.75) 120.75,22 ; v1(120.75,23.25) v1(120.75,23.75) v1(120.75,24.25) ; v1(120.75,25.75) v1(120.75,26.27) v1(120.75,26.75)
  F5 w0.2: v1(66.05,-1.3) v1@66.07,-1.3 ; v1@86.55,1.54 v1(86.55,1.6)
  F5 w0.5: v1(22.75,52) 20.88,50.13 11.18,50.13 8.32,47.27 8.32,9.61 11.65,6.28 26.29,6.28 30.42,2.15 57.69,2.15 61.14,-1.3 v1(66.05,-1.3) ; v1@66.07,-1.3 66.12,-1.25 70.15,-1.25 ; 70.25,-1.15 70.15,-1.25 ; v1(86.3,26.45) 86.3,23.63 86.63,23.3 v1(87,23.3) 87,1.99 v1@86.55,1.54 ; v1(86.55,1.6) 85.1,1.6 84.75,1.25 82,1.25 79.5,-1.25 70.15,-1.25 ; v1(87.62,23.3) 88.45,23.3 89.9,24.75 90,24.75 90,27 92.17,29.17 109.17,29.17 v1(109.25,29.25) v1@109.185,29.185 ; v1@117.893,5.75 v1(118,5.75) ; 118,5 v1(118,5.75) ; v1(120.75,21.25) v1(120.75,20.75) 120.75,19.1 119.95,18.3 119.95,11.2 118,9.25 v1(118,5.75)
  Bottom w0.2: v1(120.75,20.75) v1(120.75,21.25)
5V_ST_LINK: C76.2 JP1.3 SB9.1 U8.6 U8.7 | length 33.2
  Top w0.2: 94.6,20.25 SB9.1@95,20.25 ; v1(95.3,21.5) v1@95.35,21.55 ; v1@115.23,26.786 115.258,26.758 v1(115.25,26.75) ; 115.232,25.5 v1@115.232,25.602
  Top w0.3: v1@95.35,21.5 v1@95.35,21.55
  Top w0.5: U8.6@91.865,22.269 91.865,21.1 93.1,21.1 ; U8.7@93.135,22.269 93.1,22.269 93.1,21.1 ; v1(95.65,21.8) 95.35,21.5 v1(94.95,21.1) 94.6,20.75 94.6,20.25 C76.2@93.1,20.25 93.1,21.1 ; v1(115.25,26.25) 117.52,26.25 JP1.3@117.52,26.27
  F5 w0.2: v1@95.3,21.6 95.575,21.875 97.75,24.05
  F5 w0.5: v1(95.3,21.5) v1@95.3,21.6 ; 97.75,24.05 98.7,25 ; 98.95,25.25 98.7,25 ; v1(115.25,26.25) 107.5,26.25 107,25.75 99.45,25.75 98.7,25
  other v1: 115.25,25.75
5V_USB_FS: D3.1 JP1.5 SB18.1 | length 54.8
  Top w0.15: SB18.1@87,-4.5 87,-4.3
  Top w0.2: D3.1@103.893,21.25 v1(104.25,21.25)
  Top w0.5: v1(86.15,-4.05) 86.15,-4.1 87,-4.1 ; v1@86.5,-3.3 v1(87,-3.3) 87,-4.1 ; 87,-4.3 87,-4.1 ; 115,23.75 115.25,23.75 v1(115.25,23.73) JP1.5@117.52,23.73
  F5 w0.15: v1@115.203,24.297 v1(115.25,24.25)
  F5 w0.2: v1(87,-3.3) 87,-2.2 86.8,-2.2 90.75,1.75 90.75,11.5 101,21.75 104.75,21.75 ; v1(104.25,21.25) 104.55,21.55 104.75,21.75 ; 109.25,22.25 109.7,22.7 110,23 ; 112.75,22.5 112.75,23.2 ; 115,23.75 115.25,23.75 v1(115.25,23.73) v1(115.25,23.25) 115.25,23.2 112.75,23.2 ; 104.75,21.75 108.75,21.75 110,23 ; 110,23 110.2,23.2 112.75,23.2
  other v1: 86.4,-3.3
5V_USB_HS: CN12.1 D4.1 D7.A1 JP1.7 L6.2 | length 74.9
  Top w0.12: D7.A1@66.2,-6.2 66.525,-6.525 66.6,-6.6 v1(66.45,-6.6) ; 115.25,20.4 v1(115.25,20.75) 115.25,21.19 v1(115.25,21.25) v1(115.25,21.75) v1@115.25,21.8
  Top w0.3: v1(69.05,-6.55) v1@69.057,-6.543 ; CN12.1@69.057,-8.318 v1@69.057,-6.543 ; v1(69.5,-6.05) 69.057,-6.493 69.057,-6.5 v1@69.057,-6.543 ; D4.1@103.893,18.75 v1(104.5,18.75)
  Top w0.5: v1@69.057,-6.5 v1(69.5,-6.5) ; v1(69.5,-6.05) 69.5,-6.25 L6.2@70.65,-6.25 ; v1@115.25,21.19 JP1.7@117.519,21.19
  F5 w0.5: v1(66.45,-6.6) 66.6,-6.75 68.85,-6.75 v1(69.05,-6.55) 69.1,-6.5 v1(69.5,-6.5) 79.25,-6.5 80.85,-4.9 87.9,-4.9 87.75,-4.75 90.75,-4.75 ; 91.25,-4.75 90.75,-4.75 ; v1(115.25,21.25) v1(115.25,20.75) 115.25,20.5 106.75,12 100.75,12 96.25,7.5 96.25,0.75 90.75,-4.75
5V_USB_ST_LINK: CN14.1 D2.1 R60.2 R72.2 R120.2 SB9.2 U8.1 U8.2 | length 59.5
  Top w0.3: D2.1@97.607,21.25 v1(98.75,21.25) 98.75,20.5 98.75,20.25 98.5,20.25 ; v1(104.9,-4.1) 104.903,-4.1 CN14.1@104.903,-5.75 ; v1(111.15,-0.25) R120.2@112.15,-0.25
  Top w0.5: R60.2@93.1,29.5 93.135,29.5 U8.2@93.135,27.73 93.135,25.65 93.185,25.6 94.405,25.6 ; U8.1@94.405,27.73 94.405,25.6 ; SB9.2@96.1,20.25 98.5,20.25 98.75,20.5 ; v1(98.75,21.25) 98.75,24 97.15,25.6 94.405,25.6
  Bottom w0.3: v1(98.75,21.25) 98.75,19.25 101.25,16.75 101.25,0.55 104.35,-2.55 ; v1(104.9,-4.1) 104.9,-3.1 104.35,-2.55 ; v1(111.15,-0.25) 105,-0.25 104.35,-0.9 104.35,-2.55
AIN_1: R97.2 R98.2 U14.10 | length 6.2
  Top w0.2: R97.2@99.25,11.15 R98.2@100.5,11.15 100.5,10.45 100.65,10.3 103.2,10.3 103.5,10 U14.10@103.5,8.9
ARD_A0: CN5.1 U5.N3 | length 92
  Top w0.12: v1(31.6,39.65) U5.N3@32,39.25 ; CN5.1@111.5,41.9 111.5,41.85 v1(113.85,41.85)
  F4 w0.12: v1(31.6,39.65) 32,39.25 35.15,39.25 35.2,39.3 35.2,39.95 35.3,40.05 36.55,40.05 36.8,40.3 36.8,41.45 41.29,45.94 47.7,45.94 48.45,46.69 66.9,46.69 67.51,47.3 86.9,47.3 91.6,42.6 113.1,42.6 v1(113.85,41.85)
ARD_A1: CN5.2 U5.L1 | length 82.7
  Top w0.12: v1(33.2,41.25) U5.L1@33.6,40.85 ; v1(106.1,44.45) 108.5,44.45 CN5.2@108.5,44.44
  F4 w0.12: v1(33.2,41.25) 33.35,41.4 33.35,41.65 33.6,41.9 33.6,45.3 36.8,48.5 91.65,48.5 95.7,44.45 v1(106.1,44.45)
ARD_A2: CN5.3 U5.L2 | length 86.9
  Top w0.12: v1(33.2,40.45) U5.L2@33.6,40.05 ; v1(108.3,46.75) 108.53,46.98 CN5.3@111.5,46.98
  F4 w0.12: v1(33.2,40.45) 33.6,40.85 33.6,41.4 33.9,41.7 34.15,41.7 40.65,48.2 90.65,48.2 95.65,43.2 106.15,43.2 107.35,44.4 107.35,45.8 v1(108.3,46.75)
ARD_A3: CN5.4 U5.L3 | length 86.3
  Top w0.12: v1(33.2,39.65) U5.L3@33.6,39.25 ; v1(104.25,46.65) 107.12,49.52 CN5.4@108.5,49.52
  F4 w0.12: v1(33.2,39.65) 32.8,40.05 32.8,41.55 32.6,41.75 32.6,42.7 33,43.1 33,45.05 36.75,48.8 49.75,48.8 50.75,49.8 80.9,49.8 81.9,48.8 91.9,48.8 93.95,46.75 104.15,46.75 v1(104.25,46.65)
ARD_A4: SB5.1 U5.K1 | length 76.8
  Top w0.12: v1(34,41.25) U5.K1@34.4,40.85 ; v1(93.45,44) 99.7,50.25 SB5.1@103.25,50.25
  F4 w0.12: v1(34,41.25) 34.15,41.25 40.18,47.28 65.98,47.28 66.6,47.9 89.5,47.9 93.4,44 v1(93.45,44)
ARD_A5: SB3.1 U5.K2 | length 79.5
  Top w0.12: v1(34,40.45) U5.K2@34.4,40.05 ; v1(92.4,43.2) 92.4,44.45 101.2,53.25 SB3.1@103.25,53.25
  F4 w0.12: v1(34,40.45) 34.4,40.85 34.98,40.85 41.12,46.99 66.51,46.99 67.12,47.6 87.1,47.6 91.5,43.2 v1(92.4,43.2)
ARD_D0: CN4.1 U5.G15 | length 49.3
  Top w0.12: U5.G15@36.8,29.65 v1(37.2,29.25) ; v1(53.45,37.55) 53.45,38.2 54,38.75 54,40.75 57,43.75 57,53.1 58.5,54.6 CN4.1@60.24,54.6
  F4 w0.12: v1(37.2,29.25) 37.6,29.65 39.8,29.65 40,29.45 40,29.05 40.2,28.85 50.3,28.85 51.95,30.5 55.45,30.5 55.85,30.9 55.85,35.1 53.45,37.5 v1(53.45,37.55)
ARD_D1: CN4.2 U5.H15 | length 51.3
  Top w0.12: v1(35.6,29.25) U5.H15@36,29.65 ; v1(54.05,38.05) 54.5,38.5 54.5,40.5 57.5,43.5 57.5,50.75 58.81,52.06 CN4.2@63.24,52.06
  F4 w0.12: v1(35.6,29.25) 36.05,28.8 38.1,28.8 38.6,28.3 54.15,28.3 56.1,30.25 56.1,35.3 54.05,37.35 v1(54.05,38.05)
ARD_D2: CN4.3 U5.J15 | length 47.1
  Top w0.12: v1(34.8,29.25) U5.J15@35.2,29.65 ; v1(55.1,38.05) 55.1,40.25 58,43.15 58,49.02 58.5,49.52 CN4.3@60.24,49.52
  F4 w0.12: v1(34.8,29.25) 35.5,28.55 37.85,28.55 38.95,27.45 43.05,27.45 43.5,27.9 54.25,27.9 56.35,30 56.35,36.25 55.1,37.5 v1(55.1,38.05)
ARD_D3: CN4.4 U5.A9 | length 30.4
  Top w0.12: U5.A9@41.6,34.45 42.1,34.45 43.4,33.15 48.85,33.15 49.45,33.75 v1(50.65,33.75) ; v1(58.8,45.9) 59.88,46.98 CN4.4@63.24,46.98
  F6 w0.12: v1(50.65,33.75) 50.85,33.75 51.35,34.25 51.35,38.45 v1(58.8,45.9)
ARD_D4: CN4.5 U5.J14 | length 43.4
  Top w0.12: v1(34.8,30.05) U5.J14@35.2,30.45 ; v1(56.3,38.05) 56.3,40.5 57.3,41.5 58.75,41.5 60.24,42.99 CN4.5@60.24,44.44
  F4 w0.12: v1(34.8,30.05) 34.4,29.65 34.4,28.9 35,28.3 37.75,28.3 39,27.05 43.1,27.05 43.5,27.45 54.3,27.45 56.75,29.9 56.75,37.6 v1(56.3,38.05)
ARD_D5: CN4.6 U5.E14 | length 32
  Top w0.12: U5.E14@38.4,30.45 v1(38.8,30.05) ; v1(54.1,35) 55.05,35 58.1,38.05 61.9,38.05 63.24,39.39 CN4.6@63.24,41.9
  F4 w0.12: v1(38.8,30.05) 39.2,30.45 42.4,30.45 42.95,31 51.2,31 54.1,33.9 v1(54.1,35)
ARD_D6: CN4.7 U5.P13 | length 33.5
  Top w0.12: v1(30.8,30.85) U5.P13@31.2,31.25 ; v1(52.05,35.65) 54.6,35.65 58.31,39.36 CN4.7@60.24,39.36
  F4 w0.12: v1(30.8,30.85) 31.2,31.25 36.2,31.25 37,32.05 44,32.05 46.35,34.4 50.8,34.4 v1(52.05,35.65)
ARD_D7: CN4.8 U5.C13 | length 32.6
  Top w0.12: U5.C13@40,31.25 v1(40.4,30.85) ; v1(60.65,35.75) 60.65,36.33 61.14,36.82 CN4.8@63.24,36.82
  F4 w0.12: v1(40.4,30.85) 40.8,31.25 50.75,31.25 52.6,33.1 52.6,37.7 53.5,38.6 59.99,38.6 60.66,37.93 60.66,35.76 v1(60.65,35.75)
ARD_D8: CN7.1 U5.C14 | length 21.9
  Top w0.12: U5.C14@40,30.45 v1(40.4,30.05) ; v1(55.2,32.7) 55.45,32.7 55.506,32.756 CN7.1@60.24,32.756
  F4 w0.12: v1(40.4,30.05) 40.8,29.65 50.75,29.65 53.8,32.7 v1(55.2,32.7)
ARD_D9: CN7.2 U5.A13 | length 22.1
  Top w0.12: U5.A13@41.6,31.25 41.65,31.2 56.15,31.2 57.134,30.216 CN7.2@63.24,30.216
ARD_D10: CN7.3 U5.F15 | length 24
  Top w0.12: U5.F15@37.6,29.65 v1(38,29.25) ; v1(51.4,29.25) 55.8,29.25 57.374,27.676 CN7.3@60.24,27.676
  F4 w0.12: v1(38,29.25) 38.65,28.6 50.75,28.6 v1(51.4,29.25)
ARD_D11: CN7.4 U5.R15 | length 39.1
  Top w0.12: U5.R15@30.4,29.65 30.4,26.65 30.7,26.35 v1(30.7,25.15) ; v1(58.05,23.4) 59.786,25.136 CN7.4@63.24,25.136
  F3 w0.12: v1(30.7,25.15) 30.7,25.2 32.95,25.2 33.95,24.2 37.8,24.2 38.25,23.75 42.05,23.75 42.5,24.2 57.25,24.2 v1(58.05,23.4)
ARD_D12: CN7.5 U5.R14 | length 39.7
  Top w0.12: v1(28.4,28.9) 28.4,29 29.85,30.45 U5.R14@30.4,30.45 ; v1(58,22.65) 60.24,22.65 CN7.5@60.24,22.596
  F3 w0.12: v1(28.4,28.9) 29.05,28.9 29.7,28.25 29.7,25.3 31.1,23.9 37.75,23.9 38.7,22.95 40.8,22.95 41.05,23.2 42.15,23.2 42.85,23.9 54.1,23.9 55.35,22.65 v1(58,22.65)
ARD_D13: CN7.6 SB8.2 U5.D14 | length 35.6
  Top w0.12: U5.D14@39.2,30.45 v1(39.6,30.05) ; v1(64.45,21.95) 63.24,20.74 CN7.6@63.24,20.056 66.15,20.056 SB8.2@66.15,20
  F3 w0.12: v1(39.6,30.05) 40,29.65 40,28.13 40.74,27.39 42.531,27.39 43.251,28.11 58.32,28.11 64.45,21.98 v1(64.45,21.95)
ARD_D14: CN2.1 CN7.9 R2.1 R46.1 SB4.1 U5.B4 | length 148
  Top w0.12: CN2.1@26.5,62.31 26.5,62.3 v1(29.8,62.3) ; U5.B4@40.8,38.45 41.2,38.85 47.15,38.85 v1(47.35,38.65) 47.35,38.75 R46.1@48.4,38.75 ; v1(54.15,56) 54.15,56.4 55,57.25 56.45,57.25 57.05,57.85 57.05,58.5 R2.1@57.1,58.5 ; v1(58.15,12.4) 58.15,12.436 CN7.9@60.24,12.436 ; v1(101.6,51.75) SB4.1@103.25,51.75
  F6 w0.12: v1(29.8,62.3) 41.8,62.3 47.9,56.2 54.1,56.2 ; v1(58.15,12.4) 58.15,16.25 57.35,17.05 57.35,19.15 55.06,21.44 55.06,23.3 52.2,26.16 52.2,27.119 49.39,29.929 49.39,32.169 47.85,33.709 47.85,38.15 v1(47.35,38.65) 48.35,39.65 48.35,41.6 54.15,47.4 v1(54.15,56) v1@54.15,56.15 ; v1(101.6,51.75) 97.4,55.95 64.35,55.95 63.06,57.24 57.54,57.24 56.25,55.95 54.35,55.95 54.225,56.075 v1@54.15,56.15 ; 54.1,56.2 54.15,56.2 v1@54.15,56.15 ; 54.1,56.2 v1@54.15,56.15
ARD_D15: CN2.3 CN7.10 R1.1 R54.1 SB1.1 U5.A7 | length 150.1
  Top w0.12: CN2.3@26.5,59.77 26.5,59.85 v1(29.3,59.85) ; U5.A7@41.6,36.05 41.65,36 43,36 43.65,36.65 46.7,36.65 47.3,36.05 v1(47.3,36) 47.8,36.5 R54.1@48.4,36.5 ; v1(53.55,55.55) 53.55,55.95 53.86,56.26 53.86,56.76 v1(54.7,57.6) 55.85,57.6 56,57.75 R1.1@56,58.5 ; v1(61.25,9.9) 61.25,9.896 CN7.10@63.24,9.896 ; v1(101.6,54.7) 103.2,54.7 SB1.1@103.25,54.75
  F6 w0.12: v1(29.3,59.85) 31.1,59.85 35.4,55.55 v1(53.55,55.55) 53.55,52.78 53.05,52.28 53.05,46.9 48.05,41.9 48.05,40.05 46.95,38.95 46.95,38.1 47.2,37.85 47.2,36.1 v1(47.3,36) 47.61,35.69 47.61,33.61 49.15,32.07 49.15,29.83 51.91,27.07 51.91,26.06 54.8,23.17 54.8,20.8 56.7,18.9 56.7,11.6 58.4,9.9 v1(61.25,9.9) ; v1(54.7,57.6) 56.15,59.05 97.25,59.05 v1(101.6,54.7)
BLGND: C64.2 C65.1 C95.1 C96.1 C97.2 L5.2 R75.1 R82.2 U10.3 U10.9 | length 34.6
  Top w0.2: v1(79.25,9.35) v1@79.25,9.353
  Top w0.3: U10.9@76.5,20.325 U10.3@77.925,20.325 78.575,20.325 78.9,20.65 R82.2@79.5,20.65 ; R82.2@79.5,20.6 R82.2@79.5,20.65 ; R75.1@79.766,23 79.766,22.166 79.5,21.9 R82.2@79.5,20.65 ; C97.2@80.47,9.353 C97.2@80.75,9.353
  Top w0.5: C64.2@70,24.147 72.473,24.147 72.75,23.87 C65.1@72.75,23.1 75.32,23.1 76.5,21.92 76.5,20.325 U10.9@76.5,20 v1(76.5,18.05) ; L5.2@74.35,10 75.1,10 75.5,10.4 C95.1@76.25,10.4 C96.1@78.25,10.4 78.25,9.75 78.647,9.353 79.25,9.353 C97.2@80.47,9.353
  Bottom w0.5: v1(76.5,18.05) 76.5,16.78 79.25,14.03 v1(79.25,9.35)
BOOT0: R42.2 R45.2 U5.E6 | length 9.6
  Top w0.12: U5.E6@38.4,36.85 v1(38.8,37.25) ; v1(43.5,39.95) 43.7,39.75 R45.2@44.6,39.75 ; R45.2@44.65,39.75 R45.2@44.6,39.75 ; R42.2@44.65,40.75 44.6,40.75 R45.2@44.6,39.75
  F5 w0.12: v1(38.8,37.25) 39.2,37.65 39.2,39 39.45,39.25 43.05,39.25 43.5,39.7 v1(43.5,39.95)
CAMERA_CLK: P1.21 R3.2 | length 2.7
  Top w0.12: R3.2@58.65,59.7 58.65,60.75 59.25,61.35 P1.21@59.25,62.175
DCMI_D0: P1.4 U5.N14 | length 75.8
  Top w0.12: v1(31.6,30.05) U5.N14@32,30.45 ; v1(67.7,63.55) 67.7,62.175 P1.4@67.75,62.175
  F5 w0.12: v1(31.6,30.05) 31.2,30.45 28.55,30.45 27.63,31.37 27.63,47.94 32.54,52.85 44.03,52.85 44.9,53.72 44.9,62.94 46.49,64.53 63.27,64.53 63.95,63.85 66.05,63.85 66.35,63.55 v1(67.7,63.55)
DCMI_D1: P1.5 U5.P15 | length 75.4
  Top w0.12: v1(30.8,29.25) U5.P15@31.2,29.65 ; P1.5@67.25,62.175 v1(67.25,64.15)
  F5 w0.12: v1(30.8,29.25) 29.4,29.25 27.36,31.29 27.36,48.46 33.63,54.73 42.92,54.73 43.8,55.61 43.8,63.26 45.35,64.81 63.94,64.81 64.6,64.15 v1(67.25,64.15)
DCMI_D2: P1.6 U5.N15 | length 74.9
  Top w0.12: v1(31.6,29.25) U5.N15@32,29.65 ; P1.6@66.75,62.175 v1(66.75,64.54)
  F5 w0.12: v1(31.6,29.25) 31.15,28.8 29.5,28.8 27.09,31.21 27.09,48.88 34.58,56.37 38.1,56.37 39.02,57.29 39.02,60.81 43.27,65.06 64.24,65.06 64.76,64.54 v1(66.75,64.54)
DCMI_D3: P1.7 U5.M15 | length 75
  Top w0.12: v1(31.6,28.6) 31.75,28.6 U5.M15@32.8,29.65 ; P1.7@66.25,62.175 66.32,62.175 v1(66.32,64.97)
  F5 w0.12: v1(31.6,28.6) 31.55,28.55 29.3,28.55 26.82,31.03 26.82,49.43 42.69,65.3 66.08,65.3 66.32,65.06 v1(66.32,64.97)
DCMI_D4: P1.8 U5.E13 | length 74.5
  Top w0.12: v1(38,31.65) U5.E13@38.4,31.25 ; v1(65.7,63.35) 65.7,62.05 65.75,62 P1.8@65.75,62.175
  F3 w0.12: v1(38,31.65) 38.4,32.05 38.4,34.45 39.1,35.15 42.05,35.15 43.3,36.4 44.4,36.4 46.05,38.05 47.88,38.05 51.29,41.46 51.29,49.84 50.94,50.19 49.77,50.19 49.71,50.25 49.71,50.37 49.77,50.43 51.09,50.43 51.15,50.49 51.15,50.61 51.09,50.67 49.77,50.67 49.71,50.73 49.71,50.85 49.77,50.91 51.09,50.91 51.15,50.97 51.15,51.09 51.09,51.15 49.77,51.15 49.71,51.21 49.71,51.33 49.77,51.39 51.09,51.39 51.15,51.45 51.15,51.57 51.09,51.63 50.49,51.63 50.43,51.69 50.43,56.37 50.37,56.43 49.77,56.43 49.71,56.49 49.71,56.61 49.77,56.67 51.09,56.67 51.15,56.73 51.15,56.85 51.09,56.91 49.77,56.91 49.71,56.97 49.71,57.09 49.77,57.15 51.09,57.15 51.15,57.21 51.15,57.33 51.09,57.39 49.77,57.39 49.71,57.45 49.71,57.57 49.77,57.63 51.09,57.63 51.15,57.69 51.15,57.81 51.09,57.87 50.49,57.87 50.43,57.93 50.43,61.6 51.03,62.2 65.44,62.2 65.7,62.46 v1(65.7,63.35)
DCMI_D5: P1.9 U5.C11 | length 75.3
  Top w0.12: U5.C11@40,32.85 v1(40.4,32.45) ; P1.9@65.25,62.175 65.25,61.1 v1(65.3,61.05)
  F3 w0.12: v1(40.4,32.45) 40,32.85 40,33.45 40.2,33.65 42.35,33.65 42.85,34.15 46.75,34.15 47.43,34.83 52.61,34.83 53.73,35.95 55.62,35.95 60.839,41.169 60.839,41.253 60.414,41.678 60.414,41.763 60.499,41.847 60.584,41.847 61.517,40.914 61.602,40.914 61.687,40.999 61.687,41.084 60.754,42.017 60.754,42.102 60.839,42.187 60.923,42.187 61.857,41.253 61.942,41.253 62.027,41.338 62.027,41.423 61.093,42.357 61.093,42.441 61.178,42.526 61.263,42.526 62.196,41.593 62.281,41.593 62.366,41.678 62.366,41.763 61.942,42.187 61.942,42.272 67.28,47.61 67.28,51.15 67.22,51.21 66.62,51.21 66.56,51.27 66.56,51.39 66.62,51.45 67.94,51.45 68,51.51 68,51.63 67.94,51.69 66.62,51.69 66.56,51.75 66.56,51.87 66.62,51.93 67.94,51.93 68,51.99 68,52.11 67.94,52.17 66.62,52.17 66.56,52.23 66.56,52.35 66.62,52.41 67.94,52.41 68,52.47 68,52.59 67.94,52.65 67.34,52.65 67.28,52.71 67.28,56.25 67.22,56.31 66.62,56.31 66.56,56.37 66.56,56.49 66.62,56.55 67.94,56.55 68,56.61 68,56.73 67.94,56.79 66.62,56.79 66.56,56.85 66.56,56.97 66.62,57.03 67.94,57.03 68,57.09 68,57.21 67.94,57.27 66.62,57.27 66.56,57.33 66.56,57.45 66.62,57.51 67.94,57.51 68,57.57 68,57.69 67.94,57.75 67.34,57.75 67.28,57.81 67.28,60.13 66.36,61.05 v1(65.3,61.05)
DCMI_D6: P1.10 U5.B1 | length 74.8
  Top w0.12: U5.B1@40.8,40.85 v1(41.2,41.25) ; v1(64.7,63.3) 64.7,62.175 P1.10@64.75,62.175
  F3 w0.12: v1(41.2,41.25) 41.2,46.84 41.26,46.9 41.86,46.9 41.92,46.96 41.92,47.08 41.86,47.14 40.54,47.14 40.48,47.2 40.48,47.32 40.54,47.38 41.86,47.38 41.92,47.44 41.92,47.56 41.86,47.62 40.54,47.62 40.48,47.68 40.48,47.8 40.54,47.86 41.86,47.86 41.92,47.92 41.92,48.04 41.86,48.1 40.54,48.1 40.48,48.16 40.48,48.28 40.54,48.34 41.14,48.34 41.2,48.4 41.2,54.1 40.21,55.09 37.86,55.09 37.27,55.68 37.27,61.14 37.21,61.2 36.61,61.2 36.55,61.26 36.55,61.38 36.61,61.44 37.93,61.44 37.99,61.5 37.99,61.62 37.93,61.68 36.61,61.68 36.55,61.74 36.55,61.86 36.61,61.92 37.93,61.92 37.99,61.98 37.99,62.1 37.93,62.16 36.61,62.16 36.55,62.22 36.55,62.34 36.61,62.4 37.93,62.4 37.99,62.46 37.99,62.58 37.93,62.64 37.33,62.64 37.27,62.7 37.27,64.91 38.41,66.05 63.81,66.05 64.7,65.16 v1(64.7,63.3)
DCMI_D7: P1.11 U5.B2 | length 74.9
  Top w0.12: U5.B2@40.8,40.05 v1(41.2,40.45) ; v1(64,63.4) 64.25,63.15 P1.11@64.25,62.175
  F3 w0.12: v1(41.2,40.45) 41.6,40.85 45.05,40.85 45.74,41.54 45.74,47.62 45.68,47.68 45.08,47.68 45.02,47.74 45.02,47.86 45.08,47.92 46.4,47.92 46.46,47.98 46.46,48.1 46.4,48.16 45.08,48.16 45.02,48.22 45.02,48.34 45.08,48.4 46.4,48.4 46.46,48.46 46.46,48.58 46.4,48.64 45.08,48.64 45.02,48.7 45.02,48.82 45.08,48.88 46.4,48.88 46.46,48.94 46.46,49.06 46.4,49.12 45.8,49.12 45.74,49.18 45.74,51.76 45.68,51.82 45.08,51.82 45.02,51.88 45.02,52 45.08,52.06 46.4,52.06 46.46,52.12 46.46,52.24 46.4,52.3 45.08,52.3 45.02,52.36 45.02,52.48 45.08,52.54 46.4,52.54 46.46,52.6 46.46,52.72 46.4,52.78 45.08,52.78 45.02,52.84 45.02,52.96 45.08,53.02 46.4,53.02 46.46,53.08 46.46,53.2 46.4,53.26 45.25,53.26 44.84,53.67 44.84,57.79 45.35,58.3 46.4,58.3 46.46,58.36 46.46,58.48 46.4,58.54 45.08,58.54 45.02,58.6 45.02,58.72 45.08,58.78 46.4,58.78 46.46,58.84 46.46,58.96 46.4,59.02 45.08,59.02 45.02,59.08 45.02,59.2 45.08,59.26 46.4,59.26 46.46,59.32 46.46,59.44 46.4,59.5 45.08,59.5 45.02,59.56 45.02,59.68 45.08,59.74 45.68,59.74 45.74,59.8 45.74,63.96 46.78,65 63.15,65 64,64.15 v1(64,63.4)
